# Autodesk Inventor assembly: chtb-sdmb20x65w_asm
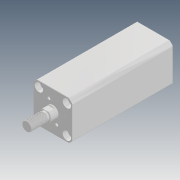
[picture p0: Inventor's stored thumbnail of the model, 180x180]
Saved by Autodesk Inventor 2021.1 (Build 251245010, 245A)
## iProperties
Company: Microsoft
Created: 2018-05
Part Number: chtb-sdmb20x65w_asm
Description: STEP AP214
Document SubType Name: Assembly
Designer: user
Title: chtb-sdmb20x65w_asm.STEP
Author: Windows
Revision Number: ÈÎºÎ
Sending System: SolidWorks 2015
Preprocessor: SwSTEP 2.0
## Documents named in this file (4)
- D:\Vault_2016\Projekty\Clamptek\Hydraulic\CHTB\CHTB-20\Inventor\CHTB-SDMB20x65W\chtb-sdmb20x65w_asm.iam
- D:\Vault_2016\Projekty\Clamptek\Hydraulic\CHTB\CHTB-20\Inventor\CHTB-SDMB20x65W\CHTB-SDMB20X65NBT.ipt
- D:\Vault_2016\Projekty\Clamptek\Hydraulic\CHTB\CHTB-20\Inventor\CHTB-SDMB20x65W\CHTB-SDMB20X65WHSG.ipt
- D:\Vault_2016\Projekty\Clamptek\Hydraulic\CHTB\CHTB-20\Inventor\CHTB-SDMB20x65W\QG_3.ipt
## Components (3 placed, 3 different names)
1. CHTB-SDMB20X65NBT_1
2. CHTB-SDMB20X65WHSG_2
3. QG_3_3
